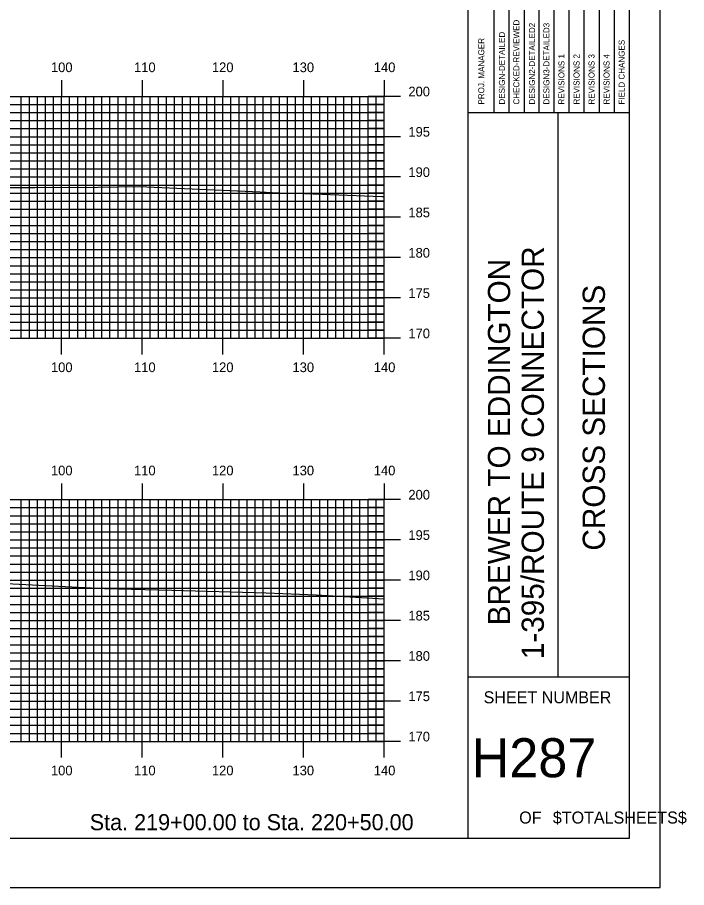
# Model space of a CAD drawing. Extents: x 1797207 to 1797550, y 442591 to 442811.
# Drawn here: x 1797467.5 to 1797550.4, y 442590.5 to 442698.5 of the extents above; entities that cross this region are included whole.
import ezdxf

# ---------------------------------------------------------------- set-up
doc = ezdxf.new("R2010")
doc.units = 0
for name, color, linetype in [('BORDER', 7, 'Continuous'), ('H_V ANNOTATION', 7, 'Continuous'), ('MAJOR', 7, 'Continuous'), ('MINOR', 7, 'Continuous'), ('PLOT BOUNDARY', 7, 'Continuous'), ('S_Roadway_Centerline', 7, 'Continuous')]:
    doc.layers.add(name, color=color, linetype=linetype)

msp = doc.modelspace()

# ---------------------------------------------------------------- linework, layer by layer
at = {"layer": 'BORDER'}
for p, q in [((1797523.33, 442596.67), (1797523.33, 442806.67)), ((1797523.33, 442686.67), (1797543.33, 442686.67)), ((1797534.51, 442616.67), (1797534.51, 442686.67)), ((1797523.33, 442616.67), (1797543.33, 442616.67))]:
    msp.add_line(p, q, dxfattribs=at)
msp.add_lwpolyline([(1797223.33, 442596.67), (1797543.33, 442596.67), (1797543.33, 442806.67), (1797223.33, 442806.67)], close=True, dxfattribs=at)
for points in [[(1797528.43, 442686.68), (1797528.43, 442721.67)], [(1797530.29, 442721.67), (1797530.29, 442686.68)], [(1797532.15, 442686.68), (1797532.15, 442721.67)], [(1797534.02, 442686.68), (1797534.02, 442721.67)], [(1797535.88, 442686.68), (1797535.88, 442721.67)], [(1797537.74, 442686.68), (1797537.74, 442721.67)], [(1797539.61, 442686.68), (1797539.61, 442721.67)], [(1797541.47, 442686.68), (1797541.47, 442721.67)], [(1797526.56, 442686.68), (1797526.56, 442720.26)]]:
    msp.add_lwpolyline(points, dxfattribs=at)
at = {"layer": 'MAJOR'}
for p, q in [((1797472.93, 442690.67), (1797472.93, 442688.67)), ((1797482.93, 442690.67), (1797482.93, 442688.67)), ((1797492.93, 442690.67), (1797492.93, 442688.67)), ((1797502.93, 442690.67), (1797502.93, 442688.67)), ((1797512.93, 442690.67), (1797512.93, 442688.67)), ((1797232.93, 442688.67), (1797512.93, 442688.67)), ((1797232.93, 442688.67), (1797512.93, 442688.67)), ((1797472.93, 442658.67), (1797472.93, 442688.67)), ((1797482.93, 442658.67), (1797482.93, 442688.67)), ((1797492.93, 442658.67), (1797492.93, 442688.67)), ((1797502.93, 442658.67), (1797502.93, 442688.67)), ((1797514.94, 442688.67), (1797510.93, 442688.67)), ((1797512.93, 442658.67), (1797512.93, 442688.67)), ((1797512.93, 442658.67), (1797512.93, 442688.67)), ((1797232.93, 442683.67), (1797512.93, 442683.67)), ((1797514.94, 442683.67), (1797510.93, 442683.67)), ((1797232.93, 442678.67), (1797512.93, 442678.67)), ((1797514.94, 442678.67), (1797510.93, 442678.67)), ((1797232.93, 442673.67), (1797512.93, 442673.67)), ((1797514.94, 442673.67), (1797510.93, 442673.67)), ((1797232.93, 442668.67), (1797512.93, 442668.67)), ((1797514.94, 442668.67), (1797510.93, 442668.67)), ((1797232.93, 442663.67), (1797512.93, 442663.67)), ((1797514.94, 442663.67), (1797510.93, 442663.67)), ((1797232.93, 442658.67), (1797512.93, 442658.67)), ((1797232.93, 442658.67), (1797512.93, 442658.67)), ((1797472.93, 442656.66), (1797472.93, 442658.67)), ((1797482.93, 442656.66), (1797482.93, 442658.67)), ((1797492.93, 442656.66), (1797492.93, 442658.67)), ((1797502.93, 442656.66), (1797502.93, 442658.67)), ((1797514.94, 442658.67), (1797510.93, 442658.67)), ((1797512.93, 442656.66), (1797512.93, 442658.67)), ((1797472.93, 442640.67), (1797472.93, 442638.67)), ((1797482.93, 442640.67), (1797482.93, 442638.67)), ((1797492.93, 442640.67), (1797492.93, 442638.67)), ((1797502.93, 442640.67), (1797502.93, 442638.67)), ((1797512.93, 442640.67), (1797512.93, 442638.67)), ((1797232.93, 442638.67), (1797512.93, 442638.67)), ((1797232.93, 442638.67), (1797512.93, 442638.67)), ((1797472.93, 442608.67), (1797472.93, 442638.67)), ((1797482.93, 442608.67), (1797482.93, 442638.67)), ((1797492.93, 442608.67), (1797492.93, 442638.67)), ((1797502.93, 442608.67), (1797502.93, 442638.67)), ((1797514.94, 442638.67), (1797510.93, 442638.67)), ((1797512.93, 442608.67), (1797512.93, 442638.67)), ((1797512.93, 442608.67), (1797512.93, 442638.67)), ((1797232.93, 442633.67), (1797512.93, 442633.67)), ((1797514.94, 442633.67), (1797510.93, 442633.67)), ((1797232.93, 442628.67), (1797512.93, 442628.67)), ((1797514.94, 442628.67), (1797510.93, 442628.67)), ((1797232.93, 442623.67), (1797512.93, 442623.67)), ((1797514.94, 442623.67), (1797510.93, 442623.67)), ((1797232.93, 442618.67), (1797512.93, 442618.67)), ((1797514.94, 442618.67), (1797510.93, 442618.67)), ((1797232.93, 442613.67), (1797512.93, 442613.67)), ((1797514.94, 442613.67), (1797510.93, 442613.67)), ((1797232.93, 442608.67), (1797512.93, 442608.67)), ((1797232.93, 442608.67), (1797512.93, 442608.67)), ((1797472.93, 442606.66), (1797472.93, 442608.67)), ((1797482.93, 442606.66), (1797482.93, 442608.67)), ((1797492.93, 442606.66), (1797492.93, 442608.67)), ((1797502.93, 442606.66), (1797502.93, 442608.67)), ((1797514.94, 442608.67), (1797510.93, 442608.67)), ((1797512.93, 442606.66), (1797512.93, 442608.67))]:
    msp.add_line(p, q, dxfattribs=at)
at = {"layer": 'MINOR'}
for p, q in [((1797467.93, 442658.67), (1797467.93, 442688.67)), ((1797468.93, 442658.67), (1797468.93, 442688.67)), ((1797469.93, 442658.67), (1797469.93, 442688.67)), ((1797470.93, 442658.67), (1797470.93, 442688.67)), ((1797471.93, 442658.67), (1797471.93, 442688.67)), ((1797473.93, 442658.67), (1797473.93, 442688.67)), ((1797474.93, 442658.67), (1797474.93, 442688.67)), ((1797475.93, 442658.67), (1797475.93, 442688.67)), ((1797476.93, 442658.67), (1797476.93, 442688.67)), ((1797477.93, 442658.67), (1797477.93, 442688.67)), ((1797478.93, 442658.67), (1797478.93, 442688.67)), ((1797479.93, 442658.67), (1797479.93, 442688.67)), ((1797480.93, 442658.67), (1797480.93, 442688.67)), ((1797481.93, 442658.67), (1797481.93, 442688.67)), ((1797483.93, 442658.67), (1797483.93, 442688.67)), ((1797484.93, 442658.67), (1797484.93, 442688.67)), ((1797485.93, 442658.67), (1797485.93, 442688.67)), ((1797486.93, 442658.67), (1797486.93, 442688.67)), ((1797487.93, 442658.67), (1797487.93, 442688.67)), ((1797488.93, 442658.67), (1797488.93, 442688.67)), ((1797489.93, 442658.67), (1797489.93, 442688.67)), ((1797490.93, 442658.67), (1797490.93, 442688.67)), ((1797491.93, 442658.67), (1797491.93, 442688.67)), ((1797493.93, 442658.67), (1797493.93, 442688.67)), ((1797494.93, 442658.67), (1797494.93, 442688.67)), ((1797495.93, 442658.67), (1797495.93, 442688.67)), ((1797496.93, 442658.67), (1797496.93, 442688.67)), ((1797497.93, 442658.67), (1797497.93, 442688.67)), ((1797498.93, 442658.67), (1797498.93, 442688.67)), ((1797499.93, 442658.67), (1797499.93, 442688.67)), ((1797500.93, 442658.67), (1797500.93, 442688.67)), ((1797501.93, 442658.67), (1797501.93, 442688.67)), ((1797503.93, 442658.67), (1797503.93, 442688.67)), ((1797504.93, 442658.67), (1797504.93, 442688.67)), ((1797505.93, 442658.67), (1797505.93, 442688.67)), ((1797506.93, 442658.67), (1797506.93, 442688.67)), ((1797507.93, 442658.67), (1797507.93, 442688.67)), ((1797508.93, 442658.67), (1797508.93, 442688.67)), ((1797509.93, 442658.67), (1797509.93, 442688.67)), ((1797510.93, 442658.67), (1797510.93, 442688.67)), ((1797511.93, 442658.67), (1797511.93, 442688.67)), ((1797232.93, 442687.67), (1797512.93, 442687.67)), ((1797512.93, 442687.67), (1797510.93, 442687.67)), ((1797232.93, 442686.67), (1797512.93, 442686.67)), ((1797512.93, 442686.67), (1797510.93, 442686.67)), ((1797232.93, 442685.67), (1797512.93, 442685.67)), ((1797512.93, 442685.67), (1797510.93, 442685.67)), ((1797232.93, 442684.67), (1797512.93, 442684.67)), ((1797512.93, 442684.67), (1797510.93, 442684.67)), ((1797232.93, 442682.67), (1797512.93, 442682.67)), ((1797512.93, 442682.67), (1797510.93, 442682.67)), ((1797232.93, 442681.67), (1797512.93, 442681.67)), ((1797512.93, 442681.67), (1797510.93, 442681.67)), ((1797232.93, 442680.67), (1797512.93, 442680.67)), ((1797232.93, 442679.67), (1797512.93, 442679.67)), ((1797512.93, 442680.67), (1797510.93, 442680.67)), ((1797512.93, 442679.67), (1797510.93, 442679.67)), ((1797232.93, 442677.67), (1797512.93, 442677.67)), ((1797512.93, 442677.67), (1797510.93, 442677.67)), ((1797232.93, 442676.67), (1797512.93, 442676.67)), ((1797512.93, 442676.67), (1797510.93, 442676.67)), ((1797232.93, 442675.67), (1797512.93, 442675.67)), ((1797512.93, 442675.67), (1797510.93, 442675.67)), ((1797232.93, 442674.67), (1797512.93, 442674.67)), ((1797512.93, 442674.67), (1797510.93, 442674.67)), ((1797232.93, 442672.67), (1797512.93, 442672.67)), ((1797512.93, 442672.67), (1797510.93, 442672.67)), ((1797232.93, 442671.67), (1797512.93, 442671.67)), ((1797512.93, 442671.67), (1797510.93, 442671.67)), ((1797232.93, 442670.67), (1797512.93, 442670.67)), ((1797512.93, 442670.67), (1797510.93, 442670.67)), ((1797232.93, 442669.67), (1797512.93, 442669.67)), ((1797512.93, 442669.67), (1797510.93, 442669.67)), ((1797232.93, 442667.67), (1797512.93, 442667.67)), ((1797512.93, 442667.67), (1797510.93, 442667.67)), ((1797232.93, 442666.67), (1797512.93, 442666.67)), ((1797232.93, 442665.67), (1797512.93, 442665.67)), ((1797512.93, 442666.67), (1797510.93, 442666.67)), ((1797512.93, 442665.67), (1797510.93, 442665.67)), ((1797232.93, 442664.67), (1797512.93, 442664.67)), ((1797512.93, 442664.67), (1797510.93, 442664.67)), ((1797232.93, 442662.67), (1797512.93, 442662.67)), ((1797512.93, 442662.67), (1797510.93, 442662.67)), ((1797232.93, 442661.67), (1797512.93, 442661.67)), ((1797512.93, 442661.67), (1797510.93, 442661.67)), ((1797232.93, 442660.67), (1797512.93, 442660.67)), ((1797512.93, 442660.67), (1797510.93, 442660.67)), ((1797232.93, 442659.67), (1797512.93, 442659.67)), ((1797512.93, 442659.67), (1797510.93, 442659.67)), ((1797467.93, 442608.67), (1797467.93, 442638.67)), ((1797468.93, 442608.67), (1797468.93, 442638.67)), ((1797469.93, 442608.67), (1797469.93, 442638.67)), ((1797470.93, 442608.67), (1797470.93, 442638.67)), ((1797471.93, 442608.67), (1797471.93, 442638.67)), ((1797473.93, 442608.67), (1797473.93, 442638.67)), ((1797474.93, 442608.67), (1797474.93, 442638.67)), ((1797475.93, 442608.67), (1797475.93, 442638.67)), ((1797476.93, 442608.67), (1797476.93, 442638.67)), ((1797477.93, 442608.67), (1797477.93, 442638.67)), ((1797478.93, 442608.67), (1797478.93, 442638.67)), ((1797479.93, 442608.67), (1797479.93, 442638.67)), ((1797480.93, 442608.67), (1797480.93, 442638.67)), ((1797481.93, 442608.67), (1797481.93, 442638.67)), ((1797483.93, 442608.67), (1797483.93, 442638.67)), ((1797484.93, 442608.67), (1797484.93, 442638.67)), ((1797485.93, 442608.67), (1797485.93, 442638.67)), ((1797486.93, 442608.67), (1797486.93, 442638.67)), ((1797487.93, 442608.67), (1797487.93, 442638.67)), ((1797488.93, 442608.67), (1797488.93, 442638.67)), ((1797489.93, 442608.67), (1797489.93, 442638.67)), ((1797490.93, 442608.67), (1797490.93, 442638.67)), ((1797491.93, 442608.67), (1797491.93, 442638.67)), ((1797493.93, 442608.67), (1797493.93, 442638.67)), ((1797494.93, 442608.67), (1797494.93, 442638.67)), ((1797495.93, 442608.67), (1797495.93, 442638.67)), ((1797496.93, 442608.67), (1797496.93, 442638.67)), ((1797497.93, 442608.67), (1797497.93, 442638.67)), ((1797498.93, 442608.67), (1797498.93, 442638.67)), ((1797499.93, 442608.67), (1797499.93, 442638.67)), ((1797500.93, 442608.67), (1797500.93, 442638.67)), ((1797501.93, 442608.67), (1797501.93, 442638.67)), ((1797503.93, 442608.67), (1797503.93, 442638.67)), ((1797504.93, 442608.67), (1797504.93, 442638.67)), ((1797505.93, 442608.67), (1797505.93, 442638.67)), ((1797506.93, 442608.67), (1797506.93, 442638.67)), ((1797507.93, 442608.67), (1797507.93, 442638.67)), ((1797508.93, 442608.67), (1797508.93, 442638.67)), ((1797509.93, 442608.67), (1797509.93, 442638.67)), ((1797510.93, 442608.67), (1797510.93, 442638.67)), ((1797511.93, 442608.67), (1797511.93, 442638.67)), ((1797232.93, 442637.67), (1797512.93, 442637.67)), ((1797512.93, 442637.67), (1797510.93, 442637.67)), ((1797232.93, 442636.67), (1797512.93, 442636.67)), ((1797512.93, 442636.67), (1797510.93, 442636.67)), ((1797232.93, 442635.67), (1797512.93, 442635.67)), ((1797512.93, 442635.67), (1797510.93, 442635.67)), ((1797232.93, 442634.67), (1797512.93, 442634.67)), ((1797512.93, 442634.67), (1797510.93, 442634.67)), ((1797232.93, 442632.67), (1797512.93, 442632.67)), ((1797512.93, 442632.67), (1797510.93, 442632.67)), ((1797232.93, 442631.67), (1797512.93, 442631.67)), ((1797512.93, 442631.67), (1797510.93, 442631.67)), ((1797232.93, 442630.67), (1797512.93, 442630.67)), ((1797512.93, 442630.67), (1797510.93, 442630.67)), ((1797232.93, 442629.67), (1797512.93, 442629.67)), ((1797512.93, 442629.67), (1797510.93, 442629.67)), ((1797232.93, 442627.67), (1797512.93, 442627.67)), ((1797512.93, 442627.67), (1797510.93, 442627.67)), ((1797232.93, 442626.67), (1797512.93, 442626.67)), ((1797512.93, 442626.67), (1797510.93, 442626.67)), ((1797232.93, 442625.67), (1797512.93, 442625.67)), ((1797232.93, 442624.67), (1797512.93, 442624.67)), ((1797512.93, 442625.67), (1797510.93, 442625.67)), ((1797512.93, 442624.67), (1797510.93, 442624.67)), ((1797232.93, 442622.67), (1797512.93, 442622.67)), ((1797512.93, 442622.67), (1797510.93, 442622.67)), ((1797232.93, 442621.67), (1797512.93, 442621.67)), ((1797512.93, 442621.67), (1797510.93, 442621.67)), ((1797232.93, 442620.67), (1797512.93, 442620.67)), ((1797512.93, 442620.67), (1797510.93, 442620.67)), ((1797232.93, 442619.67), (1797512.93, 442619.67)), ((1797512.93, 442619.67), (1797510.93, 442619.67)), ((1797232.93, 442617.67), (1797512.93, 442617.67)), ((1797512.93, 442617.67), (1797510.93, 442617.67)), ((1797232.93, 442616.67), (1797512.93, 442616.67)), ((1797512.93, 442616.67), (1797510.93, 442616.67)), ((1797232.93, 442615.67), (1797512.93, 442615.67)), ((1797512.93, 442615.67), (1797510.93, 442615.67)), ((1797232.93, 442614.67), (1797512.93, 442614.67)), ((1797512.93, 442614.67), (1797510.93, 442614.67)), ((1797232.93, 442612.67), (1797512.93, 442612.67)), ((1797232.93, 442611.67), (1797512.93, 442611.67)), ((1797512.93, 442612.67), (1797510.93, 442612.67)), ((1797512.93, 442611.67), (1797510.93, 442611.67)), ((1797232.93, 442610.67), (1797512.93, 442610.67)), ((1797512.93, 442610.67), (1797510.93, 442610.67)), ((1797232.93, 442609.67), (1797512.93, 442609.67)), ((1797512.93, 442609.67), (1797510.93, 442609.67))]:
    msp.add_line(p, q, dxfattribs=at)
at = {"layer": 'PLOT BOUNDARY'}
msp.add_lwpolyline([(1797207.14, 442590.55), (1797547.14, 442590.55), (1797547.14, 442810.55), (1797207.14, 442810.55)], close=True, dxfattribs=at)
at = {"layer": 'S_Roadway_Centerline'}
for points in [[(1797461.77, 442677.35), (1797469.61, 442677.36), (1797477.41, 442677.41), (1797482.53, 442677.47), (1797497.55, 442676.83), (1797500.57, 442676.67), (1797503.04, 442676.61), (1797512.64, 442676.24), (1797512.93, 442676.25)], [(1797458.68, 442628.65), (1797478.23, 442627.63), (1797486.59, 442627.44), (1797498.28, 442627.09), (1797504.48, 442626.85), (1797512.93, 442626.34)]]:
    msp.add_lwpolyline(points, dxfattribs=at)

# ---------------------------------------------------------------- texts
at = {"layer": 'BORDER'}
for s, height, p in [('CHECKED-REVIEWED', 0.7455, (1797529.69, 442687.65)), ('DESIGN2-DETAILED2', 0.7455, (1797531.63, 442687.65)), ('DESIGN3-DETAILED3', 0.7455, (1797533.42, 442687.65)), ('PROJ. MANAGER', 0.7455, (1797525.34, 442687.65)), ('DESIGN-DETAILED', 0.7455, (1797527.9, 442687.65)), ('FIELD CHANGES', 0.7455, (1797542.74, 442687.65)), ('REVISIONS 1', 0.7455, (1797535.28, 442687.65)), ('REVISIONS 2', 0.7455, (1797537.15, 442687.65)), ('REVISIONS 3', 0.7455, (1797539.01, 442687.65)), ('REVISIONS 4', 0.7455, (1797540.87, 442687.65)), ('1-395/ROUTE 9 CONNECTOR', 2.7557, (1797532.73, 442618.87)), ('BREWER TO EDDINGTON', 2.7557, (1797528.55, 442623.07)), ('CROSS SECTIONS', 2.7557, (1797540.3, 442632.34))]:
    msp.add_text(s, height=height, rotation=90, dxfattribs=at).set_placement(p)
for s, height, p in [('SHEET NUMBER', 1.4905, (1797525.26, 442613.4)), ('H287', 4.839, (1797523.77, 442604.23)), ('OF', 1.491, (1797529.67, 442598.49)), ('$TOTALSHEETS$', 1.4905, (1797533.84, 442598.49))]:
    msp.add_text(s, height=height, dxfattribs=at).set_placement(p)
at = {"layer": 'H_V ANNOTATION'}
for s, height, p in [('100', 1.2, (1797471.61, 442691.67)), ('110', 1.2, (1797481.91, 442691.67)), ('120', 1.2, (1797491.57, 442691.67)), ('130', 1.2, (1797501.56, 442691.67)), ('140', 1.2, (1797511.64, 442691.67)), ('200', 1.2, (1797515.93, 442688.67)), ('195', 1.2, (1797515.93, 442683.67)), ('190', 1.2, (1797515.93, 442678.67)), ('185', 1.2, (1797515.93, 442673.67)), ('180', 1.2, (1797515.93, 442668.67)), ('175', 1.2, (1797515.93, 442663.67)), ('170', 1.2, (1797515.93, 442658.67)), ('100', 1.2, (1797471.61, 442654.47)), ('110', 1.2, (1797481.91, 442654.47)), ('120', 1.2, (1797491.57, 442654.47)), ('130', 1.2, (1797501.56, 442654.47)), ('140', 1.2, (1797511.64, 442654.47)), ('100', 1.2, (1797471.61, 442641.67)), ('110', 1.2, (1797481.91, 442641.67)), ('120', 1.2, (1797491.57, 442641.67)), ('130', 1.2, (1797501.56, 442641.67)), ('140', 1.2, (1797511.64, 442641.67)), ('200', 1.2, (1797515.93, 442638.67)), ('195', 1.2, (1797515.93, 442633.67)), ('190', 1.2, (1797515.93, 442628.67)), ('185', 1.2, (1797515.93, 442623.67)), ('180', 1.2, (1797515.93, 442618.67)), ('175', 1.2, (1797515.93, 442613.67)), ('170', 1.2, (1797515.93, 442608.67)), ('100', 1.2, (1797471.61, 442604.47)), ('110', 1.2, (1797481.91, 442604.47)), ('120', 1.2, (1797491.57, 442604.47)), ('130', 1.2, (1797501.56, 442604.47)), ('140', 1.2, (1797511.64, 442604.47)), ('Sta. 219+00.00 to Sta. 220+50.00', 2.0004, (1797476.42, 442597.66))]:
    msp.add_text(s, height=height, dxfattribs=at).set_placement(p)

doc.saveas('drawing.dxf')
